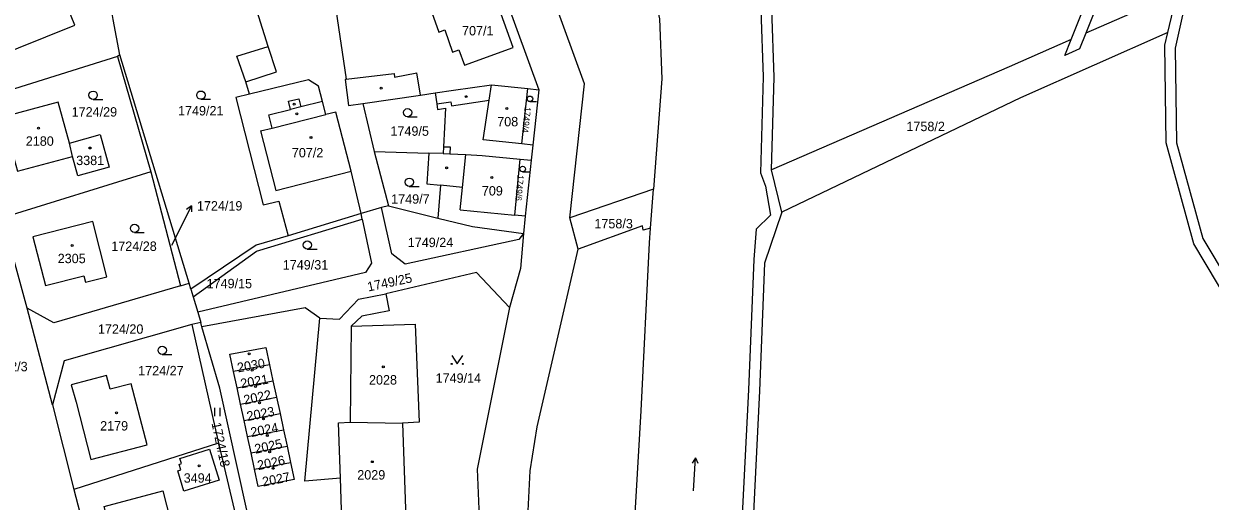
# Model space of a CAD drawing. Extents: x -679220 to -673243, y -1075091 to -1066557.
# Drawn here: x -676635.3 to -676420.8, y -1072173.8 to -1072087.4 of the extents above; entities that cross this region are included whole.
import ezdxf

# ---------------------------------------------------------------- set-up
doc = ezdxf.new("R2010")
doc.units = 0
for name, color, linetype in [('Hranice parcel', 7, 'Continuous'), ('Parcelní čísla', 7, 'Continuous'), ('Pop  PČ popisy', 7, 'Continuous'), ('Vnitřní kresba', 7, 'Continuous'), ('Značky budov', 7, 'Continuous'), ('Značky kultur', 7, 'Continuous')]:
    doc.layers.add(name, color=color, linetype=linetype)

msp = doc.modelspace()

# ---------------------------------------------------------------- linework, layer by layer
at = {"layer": 'Hranice parcel'}
for p, q in [((-676552.37, -1072071.2), (-676542.21, -1072099.31)), ((-676445.97, -1072090.24), (-676441.35, -1072078.63)), ((-676426.83, -1072081.87), (-676443.33, -1072089.08)), ((-676618.37, -1072093.31), (-676644.62, -1072101.51)), ((-676617.93, -1072092.96), (-676618.37, -1072093.31)), ((-676618.37, -1072093.31), (-676612.35, -1072114.16)), ((-676605.41, -1072134.3), (-676617.93, -1072092.96)), ((-676583.85, -1072097.51), (-676594.51, -1072100.12)), ((-676582.01, -1072098.63), (-676583.85, -1072097.51)), ((-676594.51, -1072100.12), (-676596.98, -1072100.73)), ((-676596.98, -1072100.73), (-676592.02, -1072120.1)), ((-676544.2, -1072099.1), (-676542.21, -1072099.31)), ((-676542.21, -1072099.31), (-676543.27, -1072109.32)), ((-676574.01, -1072101.78), (-676571.98, -1072110.46)), ((-676626.49, -1072111.38), (-676627.04, -1072108.94)), ((-676543.27, -1072109.32), (-676543.56, -1072112.03)), ((-676571.98, -1072110.46), (-676562.09, -1072110.75)), ((-676571.98, -1072110.46), (-676569.4, -1072120.29)), ((-676559.49, -1072110.86), (-676562.09, -1072110.75)), ((-676545.55, -1072111.84), (-676543.56, -1072112.03)), ((-676543.56, -1072112.03), (-676544.64, -1072122.16)), ((-676498.25, -1072121.48), (-676500.11, -1072113.78)), ((-676612.35, -1072114.16), (-676639.14, -1072122.45)), ((-676612.35, -1072114.16), (-676607.01, -1072134.77)), ((-676521.47, -1072117.29), (-676536.59, -1072122.5)), ((-676522, -1072124.37), (-676521.47, -1072117.29)), ((-676569.4, -1072120.29), (-676570.67, -1072120.61)), ((-676569.4, -1072120.29), (-676560.46, -1072122.55)), ((-676634.73, -1072138.81), (-676639.14, -1072122.45)), ((-676574.34, -1072121.72), (-676587.54, -1072125.71)), ((-676570.67, -1072120.61), (-676574.34, -1072121.72)), ((-676574.13, -1072122.74), (-676574.34, -1072121.72)), ((-676544.64, -1072122.16), (-676544.98, -1072125.33)), ((-676535.08, -1072128.13), (-676536.59, -1072122.5)), ((-676607.01, -1072134.77), (-676605.41, -1072134.3)), ((-676605.09, -1072135.36), (-676605.41, -1072134.3)), ((-676605.09, -1072135.36), (-676604.68, -1072136.77)), ((-676604.68, -1072136.77), (-676603.86, -1072139.57)), ((-676630.15, -1072156.31), (-676634.73, -1072138.81)), ((-676603.86, -1072139.57), (-676603.33, -1072141.39)), ((-676603.33, -1072141.39), (-676604.91, -1072141.8)), ((-676604.91, -1072141.8), (-676600.13, -1072163.22)), ((-676603.1, -1072142.19), (-676603.33, -1072141.39)), ((-676590.9, -1072149.06), (-676597.39, -1072150.28)), ((-676596.76, -1072153.23), (-676597.39, -1072150.28)), ((-676590.9, -1072149.06), (-676590.26, -1072152)), ((-676596.76, -1072153.23), (-676590.26, -1072152)), ((-676590.26, -1072152), (-676589.63, -1072154.94)), ((-676596.12, -1072156.17), (-676596.76, -1072153.23)), ((-676630.15, -1072156.31), (-676626.28, -1072171.65)), ((-676596.12, -1072156.17), (-676589.63, -1072154.94)), ((-676595.48, -1072159.12), (-676596.12, -1072156.17)), ((-676589.63, -1072154.94), (-676588.99, -1072157.89)), ((-676595.48, -1072159.12), (-676588.99, -1072157.89)), ((-676588.99, -1072157.89), (-676588.36, -1072160.82)), ((-676594.85, -1072162.06), (-676595.48, -1072159.12)), ((-676594.85, -1072162.06), (-676588.36, -1072160.82)), ((-676588.36, -1072160.82), (-676587.72, -1072163.78)), ((-676600.13, -1072163.22), (-676626.28, -1072171.65)), ((-676600.13, -1072163.22), (-676595.53, -1072182.68)), ((-676594.21, -1072165.02), (-676594.85, -1072162.06)), ((-676594.21, -1072165.02), (-676587.72, -1072163.78)), ((-676593.58, -1072167.98), (-676594.21, -1072165.02)), ((-676587.72, -1072163.78), (-676587.08, -1072166.73)), ((-676593.58, -1072167.98), (-676587.08, -1072166.73)), ((-676626.28, -1072171.65), (-676621.19, -1072191.08))]:
    msp.add_line(p, q, dxfattribs=at)
for points in [[(-676536.59, -1072122.5), (-676533.92, -1072098.22), (-676545.12, -1072067.43), (-676565.16, -1072040.09), (-676600.33, -1072005.09), (-676616.66, -1071979.22), (-676622.81, -1071969.28), (-676636.28, -1071948.34), (-676643.38, -1071915.55), (-676643.27, -1071912.66), (-676641.57, -1071878.93), (-676640.51, -1071869.39), (-676644.08, -1071858.21), (-676648.12, -1071848.64), (-676652.14, -1071843.11), (-676662.12, -1071830.1), (-676667.77, -1071822.29), (-676671.63, -1071816.16), (-676675.84, -1071808.46), (-676684.53, -1071784.41), (-676687.42, -1071776.51), (-676692.78, -1071762.77), (-676693.21, -1071759.8)], [(-676295.13, -1071902.52), (-676296.41, -1071905.95), (-676304.35, -1071909.5), (-676364.66, -1071925.74), (-676375.64, -1071931.09), (-676382.94, -1071938.2), (-676387.67, -1071944.57), (-676393.17, -1071962.19), (-676409.55, -1072024.04), (-676425.12, -1072082.52), (-676427.14, -1072091.8), (-676426.89, -1072108.9), (-676422.15, -1072126.21), (-676412.96, -1072141.55), (-676403.18, -1072152.89), (-676393.86, -1072163.85), (-676389.15, -1072169.1)], [(-676500.11, -1072113.78), (-676499.62, -1072097.03), (-676500.1, -1072084.73), (-676503.89, -1072069.84), (-676509.41, -1072056.04), (-676517.24, -1072043.14), (-676527.22, -1072031.51), (-676540.33, -1072017.45), (-676546.23, -1072009.34), (-676548.7, -1071999.72), (-676547, -1071992.02)], [(-676541.89, -1072018.69), (-676528.74, -1072032.82), (-676518.66, -1072044.42), (-676511.2, -1072056.95), (-676505.9, -1072070.52), (-676502.09, -1072084.93), (-676501.62, -1072096.94), (-676502.1, -1072114.34), (-676501.22, -1072116.73), (-676500.34, -1072121.98), (-676502.88, -1072124.51), (-676503.32, -1072130.04), (-676504.31, -1072153.57), (-676506.28, -1072192.84), (-676507.47, -1072212.67), (-676507.15, -1072233.46), (-676502.3, -1072253.2), (-676493.52, -1072270.33), (-676481.52, -1072286.7), (-676450.04, -1072327.35), (-676442.42, -1072339.58), (-676438, -1072351.9), (-676440.64, -1072365.35)], [(-676412.72, -1072028.49), (-676415.04, -1072029.73), (-676423.02, -1072046.32), (-676428.56, -1072053.03), (-676432.42, -1072061.72), (-676443.33, -1072089.08)], [(-676553.76, -1072031.84), (-676533.17, -1072054.44), (-676527.24, -1072064.82), (-676522.81, -1072075.75), (-676520.39, -1072086.47), (-676519.96, -1072097.33), (-676521.47, -1072117.29)], [(-676594.51, -1072100.12), (-676595.19, -1072097.87), (-676596.79, -1072093.24), (-676591.16, -1072091.48), (-676593.83, -1072082.77), (-676587.32, -1072080.15), (-676587.05, -1072081.24), (-676580.38, -1072079)], [(-676633.27, -1072083.18), (-676634.85, -1072083.83), (-676636.08, -1072080.81), (-676645.34, -1072084.58), (-676641.57, -1072093.86), (-676626.06, -1072087.6), (-676628.17, -1072082.38), (-676632.86, -1072084.2), (-676633.27, -1072083.18)], [(-676617.93, -1072092.96), (-676619.14, -1072086.6), (-676619.88, -1072082.19)], [(-676579.5, -1072081.87), (-676578.52, -1072084.67), (-676578.9, -1072084.79), (-676577.03, -1072097.37), (-676577.24, -1072097.44), (-676576.6, -1072102.13), (-676574.01, -1072101.78)], [(-676428.47, -1072088.93), (-676426.88, -1072082.04), (-676426.83, -1072081.87)], [(-676445.97, -1072090.24), (-676457.17, -1072095.13), (-676500.11, -1072113.78)], [(-676428.47, -1072088.93), (-676455.09, -1072100.76), (-676498.25, -1072121.48)], [(-676443.33, -1072089.08), (-676444.46, -1072091.92), (-676447.12, -1072093.11), (-676445.97, -1072090.24)], [(-676388.43, -1072172.78), (-676395.38, -1072164.99), (-676399.97, -1072163.86), (-676404.47, -1072158.39), (-676404.9, -1072153.76), (-676415.03, -1072141.81), (-676423.77, -1072127.19), (-676428.78, -1072108.88), (-676429, -1072091.21), (-676428.47, -1072088.93)], [(-676574.34, -1072121.72), (-676576.12, -1072114.04), (-676578.91, -1072103.36), (-676580.68, -1072103.8), (-676581.28, -1072101.44), (-676582.01, -1072098.63)], [(-676560.94, -1072099.88), (-676557.61, -1072099.37), (-676550.73, -1072098.39), (-676544.2, -1072099.1)], [(-676574.01, -1072101.78), (-676563.61, -1072100.27), (-676560.94, -1072099.88)], [(-676560.94, -1072099.88), (-676560.66, -1072101.86), (-676560.51, -1072102.85), (-676559.1, -1072102.64), (-676559.43, -1072109.61), (-676559.49, -1072110.86)], [(-676543.27, -1072109.32), (-676545.27, -1072109.11), (-676544.2, -1072099.1)], [(-676627.04, -1072108.94), (-676629.07, -1072101.52), (-676639.19, -1072104.29), (-676636.48, -1072114.02), (-676626.49, -1072111.38)], [(-676627.04, -1072108.94), (-676621.51, -1072107.43), (-676619.89, -1072113.34), (-676625.53, -1072114.9), (-676626.49, -1072111.38)], [(-676562.09, -1072110.75), (-676562.45, -1072116.32), (-676559.97, -1072116.58), (-676560.46, -1072122.55)], [(-676559.49, -1072110.86), (-676558.29, -1072110.92), (-676555.39, -1072111.04), (-676552.45, -1072111.17), (-676545.55, -1072111.84)], [(-676544.64, -1072122.16), (-676546.55, -1072121.99), (-676545.55, -1072111.84)], [(-676592.02, -1072120.1), (-676589.21, -1072119.47), (-676587.54, -1072125.71)], [(-676544.98, -1072125.33), (-676545.8, -1072126.42), (-676566.37, -1072130.86), (-676568.75, -1072129.02), (-676570.67, -1072120.61)], [(-676560.46, -1072122.55), (-676554.16, -1072124.03), (-676544.98, -1072125.33)], [(-676498.25, -1072121.48), (-676501.4, -1072130.67), (-676502.29, -1072153.75), (-676504.21, -1072193.03), (-676505.46, -1072212.8), (-676505.16, -1072233.19), (-676500.12, -1072252.58), (-676491.86, -1072269.13), (-676479.84, -1072285.61), (-676448.34, -1072326.26), (-676440.47, -1072338.92), (-676436.01, -1072351.82), (-676434.8, -1072359.89)], [(-676622.86, -1072123.12), (-676633.66, -1072125.89), (-676631.39, -1072134.75), (-676624.46, -1072132.96), (-676624.16, -1072134.14), (-676620.28, -1072133.14), (-676622.86, -1072123.12)], [(-676604.68, -1072136.77), (-676593.22, -1072128.5), (-676574.13, -1072122.74)], [(-676574.13, -1072122.74), (-676572.44, -1072130.71), (-676573.51, -1072132.34), (-676603.86, -1072139.57)], [(-676522, -1072124.37), (-676523.33, -1072124.68), (-676523.48, -1072123.9), (-676535.08, -1072128.13)], [(-676459.56, -1072350.97), (-676462.01, -1072344.52), (-676467.19, -1072336.72), (-676484.08, -1072315.1), (-676500.58, -1072293.17), (-676511.67, -1072277.21), (-676520.52, -1072259.37), (-676526.16, -1072238.16), (-676527.35, -1072218.91), (-676525.48, -1072188.37), (-676523.69, -1072157.38), (-676522.2, -1072127.02), (-676522, -1072124.37)], [(-676587.54, -1072125.71), (-676593.33, -1072127.44), (-676605.09, -1072135.36)], [(-676544.98, -1072125.33), (-676545.54, -1072131.64), (-676547.48, -1072138.71)], [(-676478.96, -1072345.25), (-676486.76, -1072334.9), (-676494.15, -1072325.32), (-676502.31, -1072314.41), (-676514.96, -1072297.26), (-676522.29, -1072287.64), (-676529.49, -1072277.98), (-676533.98, -1072271.49), (-676535.89, -1072267.87), (-676539.19, -1072260.61), (-676540.03, -1072256.53), (-676540.61, -1072252.56), (-676541.33, -1072240.55), (-676542.21, -1072228.4), (-676543.04, -1072216.44), (-676543.58, -1072204.41), (-676544.01, -1072192.29), (-676544.34, -1072180.34), (-676543.76, -1072168.24), (-676542.51, -1072160.31), (-676535.08, -1072128.13)], [(-676547.48, -1072138.71), (-676553.48, -1072132.36), (-676569.88, -1072136.21)], [(-676607.01, -1072134.77), (-676629.87, -1072141.5), (-676634.73, -1072138.81)], [(-676581.79, -1072140.66), (-676578.22, -1072140.79), (-676574.82, -1072137.17), (-676569.88, -1072136.21)], [(-676569.88, -1072136.21), (-676569.26, -1072139.33), (-676574.2, -1072140.29), (-676576.14, -1072142.1), (-676564.56, -1072141.69), (-676563.86, -1072159.47), (-676566.87, -1072159.65)], [(-676581.79, -1072140.66), (-676584.42, -1072138.79), (-676603.1, -1072142.19)], [(-676547.48, -1072138.71), (-676553.33, -1072167.94), (-676552.85, -1072179.54), (-676554.08, -1072179.63)], [(-676604.91, -1072141.8), (-676628, -1072148.36), (-676630.15, -1072156.31)], [(-676578.07, -1072169.6), (-676584.51, -1072170.12), (-676581.79, -1072140.66)], [(-676593.46, -1072182.19), (-676599.85, -1072153.31), (-676603.1, -1072142.19)], [(-676597.39, -1072150.28), (-676598.06, -1072147.17), (-676591.57, -1072145.95), (-676590.9, -1072149.06)], [(-676625.84, -1072155.82), (-676623.21, -1072166.23), (-676612.99, -1072163.56), (-676615.89, -1072152.5), (-676619.71, -1072153.5), (-676620.37, -1072150.99), (-676626.72, -1072152.67), (-676625.84, -1072155.82)], [(-676578.07, -1072169.6), (-676578.43, -1072159.55), (-676576.28, -1072159.47), (-676566.87, -1072159.65)], [(-676566.87, -1072159.65), (-676566.24, -1072176.8), (-676577.79, -1072177.22), (-676578.07, -1072169.6)], [(-676607.09, -1072166.01), (-676601.74, -1072164.32), (-676600, -1072169.94), (-676606.37, -1072171.92), (-676607.47, -1072168.24), (-676606.92, -1072168.06), (-676607.24, -1072167.08), (-676606.79, -1072166.93), (-676607.09, -1072166.01)], [(-676587.08, -1072166.73), (-676586.41, -1072169.82), (-676592.91, -1072171.07), (-676593.58, -1072167.98)], [(-676618.25, -1072184.77), (-676620.81, -1072174.69), (-676610.17, -1072171.88), (-676607.61, -1072181.99), (-676618.25, -1072184.77)]]:
    msp.add_lwpolyline(points, dxfattribs=at)
at = {"layer": 'Pop  PČ popisy'}
for p, q in [((-676606.34, -1072123), (-676605.02, -1072120.3)), ((-676605.02, -1072120.3), (-676605.91, -1072120.98)), ((-676605.02, -1072120.3), (-676605.01, -1072121.42)), ((-676608.52, -1072127.4), (-676606.34, -1072123))]:
    msp.add_line(p, q, dxfattribs=at)
at = {"layer": 'Vnitřní kresba'}
for p, q in [((-676546.84, -1072091.68), (-676550.85, -1072080.53)), ((-676561.84, -1072084.49), (-676560.26, -1072088.87)), ((-676560.26, -1072088.87), (-676559.22, -1072088.49)), ((-676559.22, -1072088.49), (-676557.78, -1072092.49)), ((-676589.63, -1072096.08), (-676591.16, -1072091.48)), ((-676557.78, -1072092.49), (-676556.65, -1072092.08)), ((-676556.65, -1072092.08), (-676555.65, -1072094.88)), ((-676555.65, -1072094.88), (-676546.84, -1072091.68)), ((-676595.19, -1072097.87), (-676589.63, -1072096.08)), ((-676577.03, -1072097.37), (-676568.38, -1072096.37)), ((-676568.38, -1072096.37), (-676568.31, -1072097)), ((-676568.31, -1072097), (-676564.26, -1072096.22)), ((-676563.61, -1072100.27), (-676564.26, -1072096.22)), ((-676551.16, -1072101.16), (-676550.73, -1072098.39)), ((-676587.44, -1072101.37), (-676585.6, -1072100.92)), ((-676585.6, -1072100.92), (-676585.24, -1072102.41)), ((-676591, -1072103.82), (-676587.07, -1072102.86)), ((-676587.07, -1072102.86), (-676587.44, -1072101.37)), ((-676585.24, -1072102.41), (-676587.07, -1072102.86)), ((-676581.28, -1072101.44), (-676585.24, -1072102.41)), ((-676560.66, -1072101.86), (-676558.09, -1072101.49)), ((-676558.09, -1072101.49), (-676557.98, -1072102.23)), ((-676557.98, -1072102.23), (-676551.16, -1072101.16)), ((-676552.28, -1072108.36), (-676551.16, -1072101.16)), ((-676590.4, -1072106.23), (-676591, -1072103.82)), ((-676590.4, -1072106.23), (-676580.68, -1072103.8)), ((-676592.51, -1072106.76), (-676590.4, -1072106.23)), ((-676592.51, -1072106.76), (-676589.73, -1072117.55)), ((-676559.43, -1072109.61), (-676558.24, -1072109.62)), ((-676558.24, -1072109.62), (-676558.29, -1072110.92)), ((-676545.27, -1072109.11), (-676552.28, -1072108.36)), ((-676556.01, -1072116.99), (-676555.39, -1072111.04)), ((-676589.73, -1072117.55), (-676576.12, -1072114.04)), ((-676556.01, -1072116.99), (-676559.97, -1072116.58)), ((-676556.43, -1072121.03), (-676556.01, -1072116.99)), ((-676556.43, -1072121.03), (-676546.55, -1072121.99)), ((-676576.14, -1072142.1), (-676576.28, -1072159.47))]:
    msp.add_line(p, q, dxfattribs=at)
at = {"layer": 'Značky budov'}
for centre in [(-676570.69, -1072099.02), (-676555.35, -1072100.55), (-676586.44, -1072101.91), (-676547.96, -1072102.7), (-676585.95, -1072103.68), (-676632.66, -1072106.24), (-676623.34, -1072109.84), (-676583.39, -1072107.92), (-676558.86, -1072113.45), (-676550.7, -1072115.18), (-676626.57, -1072127.5), (-676594.58, -1072147.1), (-676594.01, -1072150.02), (-676570.31, -1072149.45), (-676593.44, -1072152.99), (-676592.72, -1072155.95), (-676618.53, -1072157.74), (-676592, -1072158.87), (-676591.28, -1072161.84), (-676590.86, -1072164.8), (-676603.61, -1072167.35), (-676590.21, -1072167.8), (-676572.3, -1072166.6)]:
    msp.add_circle(centre, 0.175, dxfattribs=at)
at = {"layer": 'Značky kultur'}
for p, q in [((-676622.78, -1072101.04), (-676621.03, -1072101.04)), ((-676603.29, -1072101.03), (-676601.54, -1072101.03)), ((-676543.81, -1072101.45), (-676542.63, -1072101.45)), ((-676565.92, -1072104.19), (-676564.17, -1072104.19)), ((-676545.11, -1072114.15), (-676543.94, -1072114.15)), ((-676565.61, -1072116.78), (-676563.86, -1072116.78)), ((-676615.29, -1072125.13), (-676613.54, -1072125.13)), ((-676584.05, -1072128.15), (-676582.3, -1072128.15)), ((-676610.29, -1072147.2), (-676608.54, -1072147.2)), ((-676600.8, -1072158.36), (-676600.8, -1072156.86)), ((-676599.8, -1072158.36), (-676599.8, -1072156.86)), ((-676513.89, -1072165.89), (-676514.45, -1072166.84)), ((-676514.21, -1072171.88), (-676513.89, -1072165.89)), ((-676513.89, -1072165.89), (-676513.44, -1072166.89))]:
    msp.add_line(p, q, dxfattribs=at)
msp.add_lwpolyline([(-676557.95, -1072147.41), (-676556.95, -1072148.91), (-676555.95, -1072147.41)], dxfattribs=at)
for centre, radius in [((-676622.78, -1072100.29), 0.75), ((-676603.29, -1072100.28), 0.75), ((-676543.81, -1072100.95), 0.502), ((-676565.92, -1072103.44), 0.75), ((-676545.12, -1072113.65), 0.502), ((-676565.61, -1072116.03), 0.75), ((-676615.29, -1072124.38), 0.75), ((-676584.05, -1072127.4), 0.75), ((-676610.29, -1072146.45), 0.75), ((-676557.95, -1072148.91), 0.1), ((-676555.95, -1072148.91), 0.1)]:
    msp.add_circle(centre, radius, dxfattribs=at)

# ---------------------------------------------------------------- texts
at = {"layer": 'Parcelní čísla'}
for s, p in [('707/1', (-676556.08, -1072089.47)), ('1724/29', (-676626.66, -1072104.16)), ('1749/21', (-676607.43, -1072103.95)), ('708', (-676549.72, -1072105.92)), ('1758/2', (-676475.74, -1072106.79)), ('1749/5', (-676569.02, -1072107.63)), ('2180', (-676634.95, -1072109.44)), ('3381', (-676625.84, -1072112.93)), ('707/2', (-676586.85, -1072111.54)), ('1749/7', (-676568.89, -1072119.92)), ('709', (-676552.5, -1072118.44)), ('1724/19', (-676604.01, -1072121.16)), ('1758/3', (-676532.15, -1072124.38)), ('1724/28', (-676619.49, -1072128.46)), ('1749/24', (-676565.89, -1072127.78)), ('2305', (-676629.18, -1072130.68)), ('1749/31', (-676588.49, -1072131.83)), ('1749/15', (-676602.26, -1072135.22)), ('1724/20', (-676621.91, -1072143.45)), ('2082/3', (-676641.57, -1072150.24)), ('1724/27', (-676614.63, -1072150.97)), ('2028', (-676572.9, -1072152.64)), ('1749/14', (-676560.86, -1072152.33)), ('2179', (-676621.51, -1072160.96)), ('3494', (-676606.4, -1072170.4)), ('2029', (-676575.02, -1072169.83))]:
    msp.add_text(s, height=1.7, dxfattribs=at).set_placement(p)
for s, height, rotation, p in [('1749/4', 1.14, 264, (-676544.75, -1072102.38)), ('1749/6', 1.14, 265, (-676546.05, -1072114.7)), ('1749/25', 1.7, 12, (-676573.02, -1072135.82)), ('2030', 1.7, 10, (-676596.58, -1072150.45)), ('2021', 1.7, 10, (-676595.98, -1072153.33)), ('2022', 1.7, 12, (-676595.38, -1072156.29)), ('2023', 1.7, 11, (-676594.83, -1072159.25)), ('1724/18', 1.7, 282, (-676601.38, -1072159.66)), ('2024', 1.7, 11, (-676594.14, -1072162.14)), ('2025', 1.7, 12, (-676593.4, -1072165.17)), ('2026', 1.7, 12, (-676592.91, -1072168.14)), ('2027', 1.7, 11, (-676592.02, -1072171.1))]:
    msp.add_text(s, height=height, rotation=rotation, dxfattribs=at).set_placement(p)

doc.saveas('drawing.dxf')
